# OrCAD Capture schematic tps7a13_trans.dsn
size A
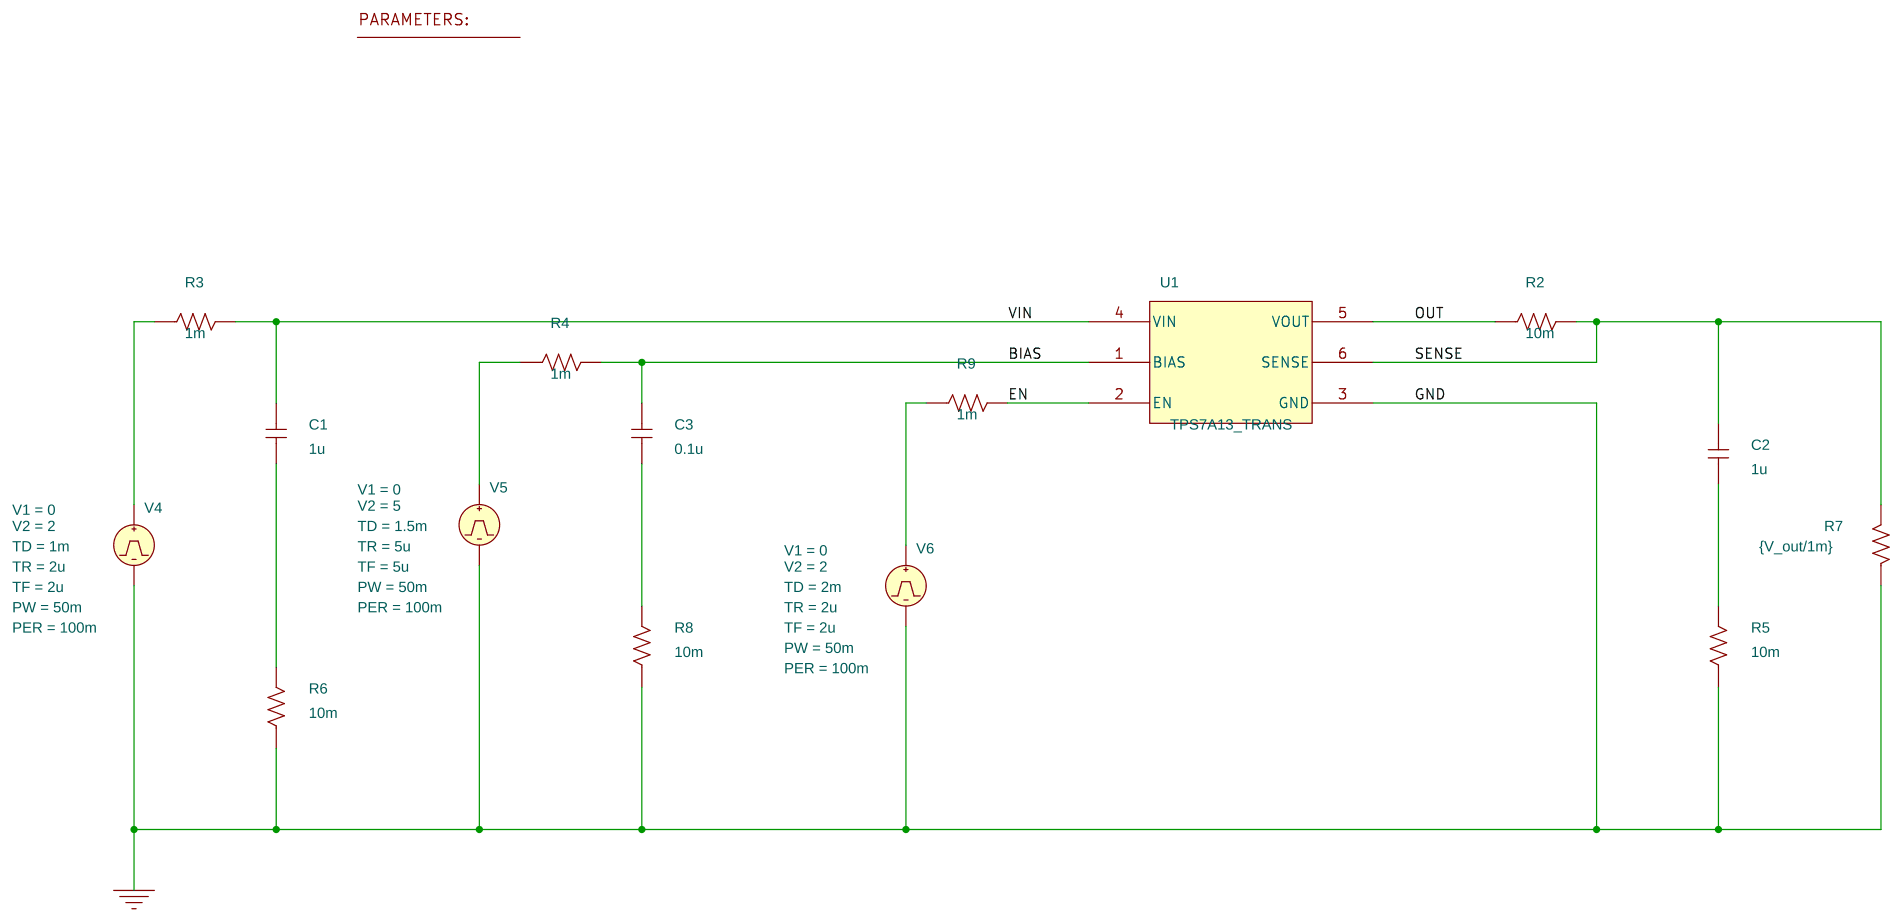
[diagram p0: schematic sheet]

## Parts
1  PARAM
C1  1u  [cap196]
C2  1u  [cap196]
C3  0.1u  [cap196]
R2  10m  [AXRC05]
R3  1m  [AXRC05]
R4  1m  [AXRC05]
R5  10m  [AXRC05]
R6  10m  [AXRC05]
R7  {V_out/1m}  [AXRC05]
R8  10m  [AXRC05]
R9  1m  [AXRC05]
U1  TPS7A13_TRANS
V4  VPULSE
V5  VPULSE
V6  VPULSE

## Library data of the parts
1 = PARAM: V_out: 0.9
C1-C3 = C
R2-R9 = R
U1 = TPS7A13_TRANS_0
V4 = VPULSE: PER: 100m; PW: 50m; TD: 1m; TF: 2u; TR: 2u; V1: 0; V2: 2
V5 = VPULSE: PER: 100m; PW: 50m; TD: 1.5m; TF: 5u; TR: 5u; V1: 0; V2: 5
V6 = VPULSE: PER: 100m; PW: 50m; TD: 2m; TF: 2u; TR: 2u; V1: 0; V2: 2

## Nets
VIN: C1.2 R3.2 U1.4(VIN)
0: R5.1 R6.1 R7.1 R8.1 U1.3(GND) V4.2(-) V5.2(-) V6.2(-)
BIAS: C3.2 R4.2 U1.1(BIAS)
EN: R9.2 U1.2(EN)
OUT: R2.1 U1.5(VOUT)
SENSE: C2.2 R2.2 R7.2 U1.6(SENSE)
N00241: R3.1 V4.1(+)
N06623: R4.1 V5.1(+)
N07169: C2.1 R5.2
N08018: C1.1 R6.2
N09513: C3.1 R8.2
N11090: R9.1 V6.1(+)
